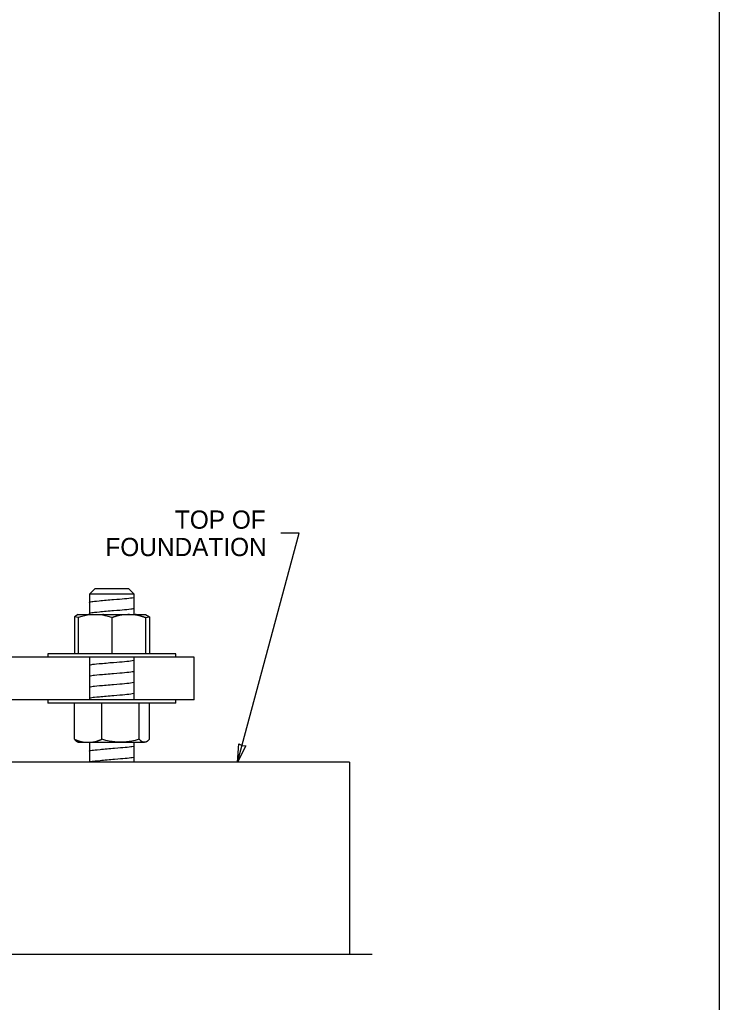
# Model space of a CAD drawing. Extents: x 99862 to 104211, y 98939 to 111076.
# Drawn here: x 102536 to 103150, y 109352 to 110214 of the extents above; entities that cross this region are included whole.
import ezdxf

# ---------------------------------------------------------------- set-up
doc = ezdxf.new("R2010")
doc.units = 0
for name, color, linetype in [('Level 15', 7, 'Continuous'), ('Level 2', 7, 'Continuous'), ('Level 20', 7, 'Continuous'), ('Level 3', 7, 'Continuous'), ('Level 60', 7, 'Continuous'), ('Level 62', 7, 'Continuous'), ('Level 9', 7, 'Continuous')]:
    doc.layers.add(name, color=color, linetype=linetype)

msp = doc.modelspace()

# ---------------------------------------------------------------- linework, layer by layer
at = {"layer": 'Level 15'}
for p, q in [((102727.51, 109562.6), (102781.5, 109763.2)), ((102781.5, 109763.2), (102765.5, 109763.2))]:
    msp.add_line(p, q, dxfattribs=at)
msp.add_lwpolyline([(102727.51, 109562.6), (102728.76, 109578.57), (102731.54, 109577.04), (102734.7, 109576.91)], close=True, dxfattribs=at)
msp.add_lwpolyline([(102845.72, 109393.85), (102367.65, 109393.85), (102367.65, 109378.37), (102336.68, 109409.34), (102336.68, 109393.85), (101810.64, 109393.85)], dxfattribs=at)
at = {"layer": 'Level 2'}
for p, q in [((102689.4, 109654.65), (101989.36, 109654.65)), ((102689.4, 109617.15), (102689.4, 109654.65)), ((102689.4, 109617.15), (101989.36, 109617.15))]:
    msp.add_line(p, q, dxfattribs=at)
for points in [[(102597.69, 109702.63), (102597.7, 109702.69), (102597.77, 109702.75), (102598.96, 109703.34), (102604.77, 109703.85), (102619.81, 109705.29), (102628.8, 109705.85), (102635.86, 109706.73), (102637.12, 109707.03), (102636.97, 109707.4)], [(102597.69, 109692.91), (102597.66, 109692.99), (102597.73, 109693.07), (102598.99, 109693.68), (102604.8, 109694.2), (102619.86, 109695.63), (102628.84, 109696.2), (102636.05, 109697.1), (102637.3, 109697.42), (102636.91, 109697.83)], [(102597.69, 109647.5), (102597.7, 109647.56), (102597.77, 109647.62), (102598.96, 109648.21), (102604.77, 109648.72), (102619.81, 109650.15), (102628.8, 109650.72), (102635.86, 109651.6), (102637.12, 109651.9), (102636.97, 109652.27)], [(102597.69, 109637.78), (102597.66, 109637.86), (102597.73, 109637.94), (102598.99, 109638.55), (102604.8, 109639.07), (102619.86, 109640.5), (102628.84, 109641.07), (102636.05, 109641.97), (102637.3, 109642.28), (102636.91, 109642.69)], [(102597.73, 109628.25), (102597.77, 109628.29), (102597.83, 109628.33), (102599.01, 109628.9), (102604.84, 109629.41), (102619.9, 109630.84), (102628.87, 109631.41), (102635.91, 109632.29), (102637.15, 109632.59), (102636.96, 109632.97)], [(102597.74, 109618.6), (102597.78, 109618.64), (102597.84, 109618.68), (102599.03, 109619.24), (102604.87, 109619.76), (102619.94, 109621.19), (102628.91, 109621.76), (102635.99, 109622.65), (102637.23, 109622.95), (102636.93, 109623.35)]]:
    msp.add_open_spline(points, degree=3, dxfattribs=at)
at = {"layer": 'Level 3'}
for p, q in [((102673.48, 109657.45), (102561.17, 109657.45)), ((102561.17, 109657.45), (102561.17, 109654.65)), ((102673.48, 109654.65), (102561.17, 109654.65)), ((102673.48, 109657.45), (102673.49, 109657.45)), ((102673.48, 109654.65), (102673.48, 109657.45)), ((102673.48, 109654.65), (102673.49, 109654.65)), ((102673.48, 109654.65), (102673.49, 109654.65)), ((102673.48, 109617.15), (102561.17, 109617.15)), ((102561.17, 109617.15), (102561.17, 109614.34)), ((102673.48, 109617.15), (102673.49, 109617.15)), ((102673.48, 109614.34), (102673.48, 109617.15)), ((102673.48, 109617.15), (102673.49, 109617.15)), ((102673.48, 109614.34), (102561.17, 109614.34)), ((102673.48, 109614.34), (102673.49, 109614.34)), ((102825.72, 109562.6), (101830.44, 109562.6)), ((102825.72, 109562.6), (102825.72, 109393.85))]:
    msp.add_line(p, q, dxfattribs=at)
at = {"layer": 'Level 60'}
msp.add_line((103150, 109000), (103150, 111075), dxfattribs=at)
at = {"layer": 'Level 62'}
for points in [[(102597.69, 109572.19), (102597.7, 109572.27), (102597.78, 109572.35), (102599.16, 109572.95), (102605.46, 109573.5), (102620.72, 109574.96), (102629.39, 109575.5), (102635.73, 109576.31), (102636.91, 109576.58), (102636.96, 109576.91)], [(102597.72, 109562.6), (102597.75, 109562.65), (102597.84, 109562.71), (102599.19, 109563.3), (102605.49, 109563.85), (102620.76, 109565.3), (102629.42, 109565.85), (102635.92, 109566.68), (102637.1, 109566.97), (102636.94, 109567.33)]]:
    msp.add_open_spline(points, degree=3, dxfattribs=at)
at = {"layer": 'Level 9'}
for p, q in [((102602.35, 109714.46), (102597.67, 109709.78)), ((102632.3, 109714.46), (102602.35, 109714.46)), ((102632.3, 109714.46), (102632.31, 109714.46)), ((102636.98, 109709.78), (102632.3, 109714.46)), ((102597.67, 109709.78), (102597.67, 109691.84)), ((102636.98, 109709.78), (102597.67, 109709.78)), ((102636.98, 109691.84), (102636.98, 109709.78)), ((102636.98, 109709.78), (102636.99, 109709.78)), ((102587.85, 109691.84), (102584.45, 109689.88)), ((102584.45, 109689.88), (102584.45, 109657.45)), ((102587.85, 109689.21), (102584.45, 109689.88)), ((102587.85, 109691.84), (102587.85, 109691.84)), ((102587.85, 109691.84), (102631.73, 109691.84)), ((102587.85, 109689.21), (102587.85, 109657.45)), ((102602.06, 109691.84), (102603.12, 109691.84)), ((102610.08, 109691.84), (102609.33, 109691.84)), ((102617.32, 109689.21), (102617.32, 109657.45)), ((102624.37, 109691.84), (102625.56, 109691.84)), ((102631.37, 109691.84), (102632.76, 109691.84)), ((102632.4, 109691.84), (102631.73, 109691.84)), ((102632.4, 109691.84), (102631.73, 109691.84)), ((102632.4, 109691.84), (102646.8, 109691.84)), ((102638.69, 109691.84), (102637.66, 109691.84)), ((102646.8, 109689.21), (102646.8, 109657.45)), ((102646.81, 109691.84), (102650.2, 109689.88)), ((102646.81, 109689.21), (102650.2, 109689.88)), ((102650.2, 109689.88), (102650.2, 109657.45)), ((102597.67, 109654.65), (102597.67, 109617.15)), ((102636.98, 109617.15), (102636.98, 109654.65)), ((102584.45, 109582.58), (102584.45, 109614.34)), ((102608.52, 109582.58), (102608.52, 109614.34)), ((102641.39, 109582.58), (102641.39, 109614.34)), ((102650.2, 109582.58), (102650.2, 109614.34)), ((102586.65, 109580.65), (102587.86, 109579.95)), ((102586.8, 109580.56), (102587.85, 109579.95)), ((102587.85, 109579.95), (102596.48, 109579.95)), ((102588.7, 109579.95), (102589.02, 109579.95)), ((102592.01, 109579.95), (102591.62, 109579.95)), ((102596.48, 109579.95), (102645.7, 109579.95)), ((102597.67, 109579.95), (102597.67, 109562.6)), ((102597.67, 109579.95), (102597.67, 109562.6)), ((102608.92, 109579.95), (102610.48, 109579.95)), ((102618.07, 109579.95), (102616.61, 109579.95)), ((102636.98, 109562.6), (102636.98, 109579.95)), ((102637.65, 109579.95), (102638.68, 109579.95)), ((102643.26, 109579.95), (102642.46, 109579.95)), ((102645.7, 109579.95), (102645.9, 109579.95)), ((102645.9, 109579.95), (102645.7, 109579.95))]:
    msp.add_line(p, q, dxfattribs=at)
for points, degree in [([(102617.32, 109689.21), (102612.51, 109690.82), (102607.62, 109691.84), (102597.6, 109691.85), (102592.67, 109690.82), (102587.85, 109689.21)], 3), ([(102631.73, 109691.84), (102626.83, 109691.8), (102622.03, 109690.78), (102617.32, 109689.21)], 2), ([(102646.8, 109689.21), (102642.09, 109690.79), (102637.31, 109691.8), (102632.4, 109691.84)], 2), ([(102584.45, 109582.58), (102585.23, 109581.71), (102586.02, 109581.01), (102586.82, 109580.55)], 2), ([(102584.45, 109582.58), (102588.37, 109580.98), (102592.41, 109579.95), (102596.48, 109579.95)], 2), ([(102596.48, 109579.95), (102600.55, 109579.95), (102604.63, 109581), (102608.52, 109582.58)], 2), ([(102641.39, 109582.58), (102636.03, 109580.98), (102630.58, 109579.96), (102619.4, 109579.95), (102613.89, 109580.98), (102608.52, 109582.58)], 3), ([(102645.7, 109579.95), (102644.24, 109579.99), (102642.8, 109581.02), (102641.39, 109582.58)], 2), ([(102650.2, 109582.58), (102648.8, 109581.01), (102647.37, 109579.99), (102645.9, 109579.95)], 2)]:
    msp.add_open_spline(points, degree=degree, dxfattribs=at)

# ---------------------------------------------------------------- texts
at = {"layer": 'Level 20'}
for s, p in [('TOP OF', (102672.61, 109767.2)), ('FOUNDATION', (102611.64, 109743.2))]:
    msp.add_text(s, height=16, rotation=360, dxfattribs=at).set_placement(p)

doc.saveas('drawing.dxf')
